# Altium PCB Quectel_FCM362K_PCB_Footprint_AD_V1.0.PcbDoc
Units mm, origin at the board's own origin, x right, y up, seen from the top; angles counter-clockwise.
Board outline 152.4 x 101.6 mm, 2 copper layers (Top Layer, Bottom Layer); 1 components, 0 nets, 47 pads, 0 vias.
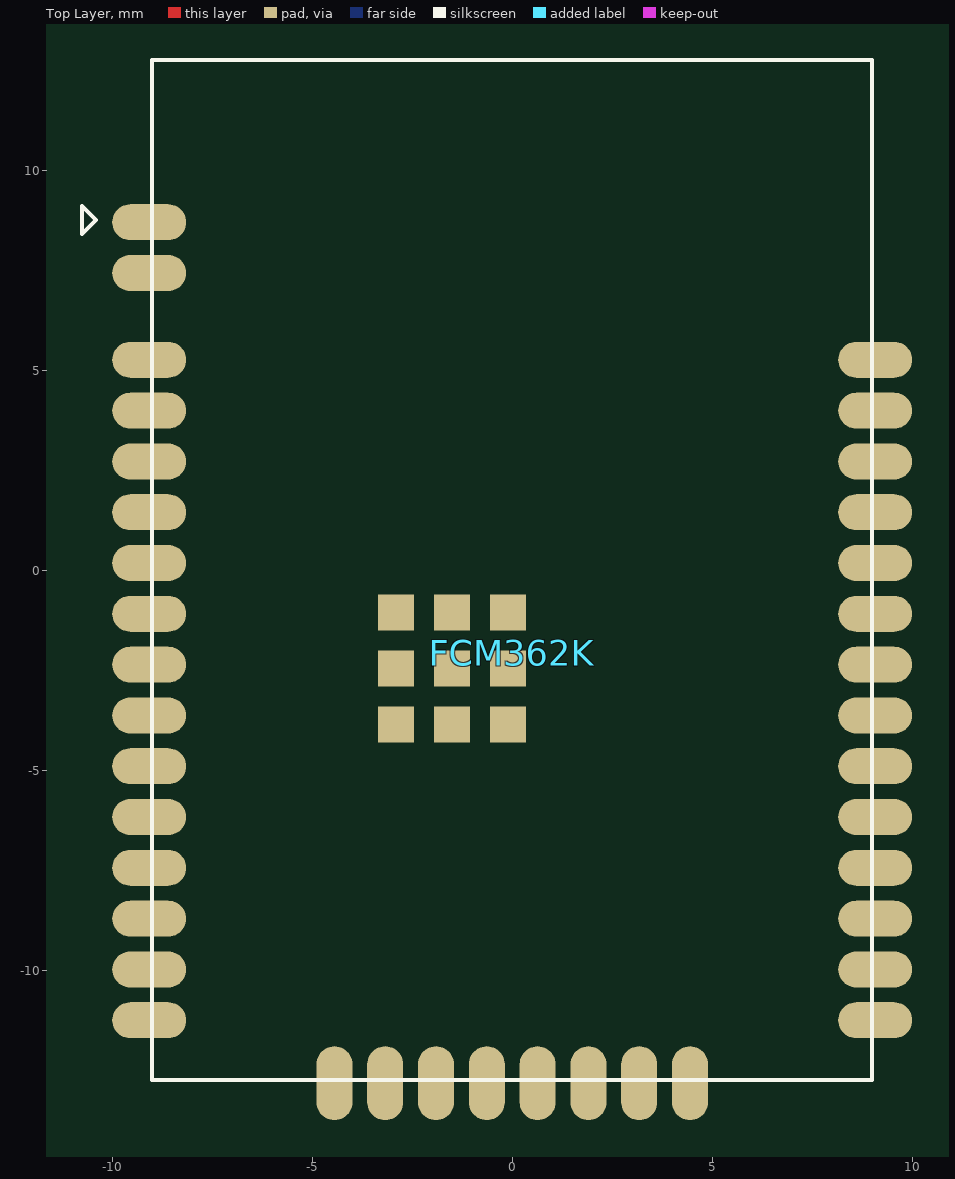
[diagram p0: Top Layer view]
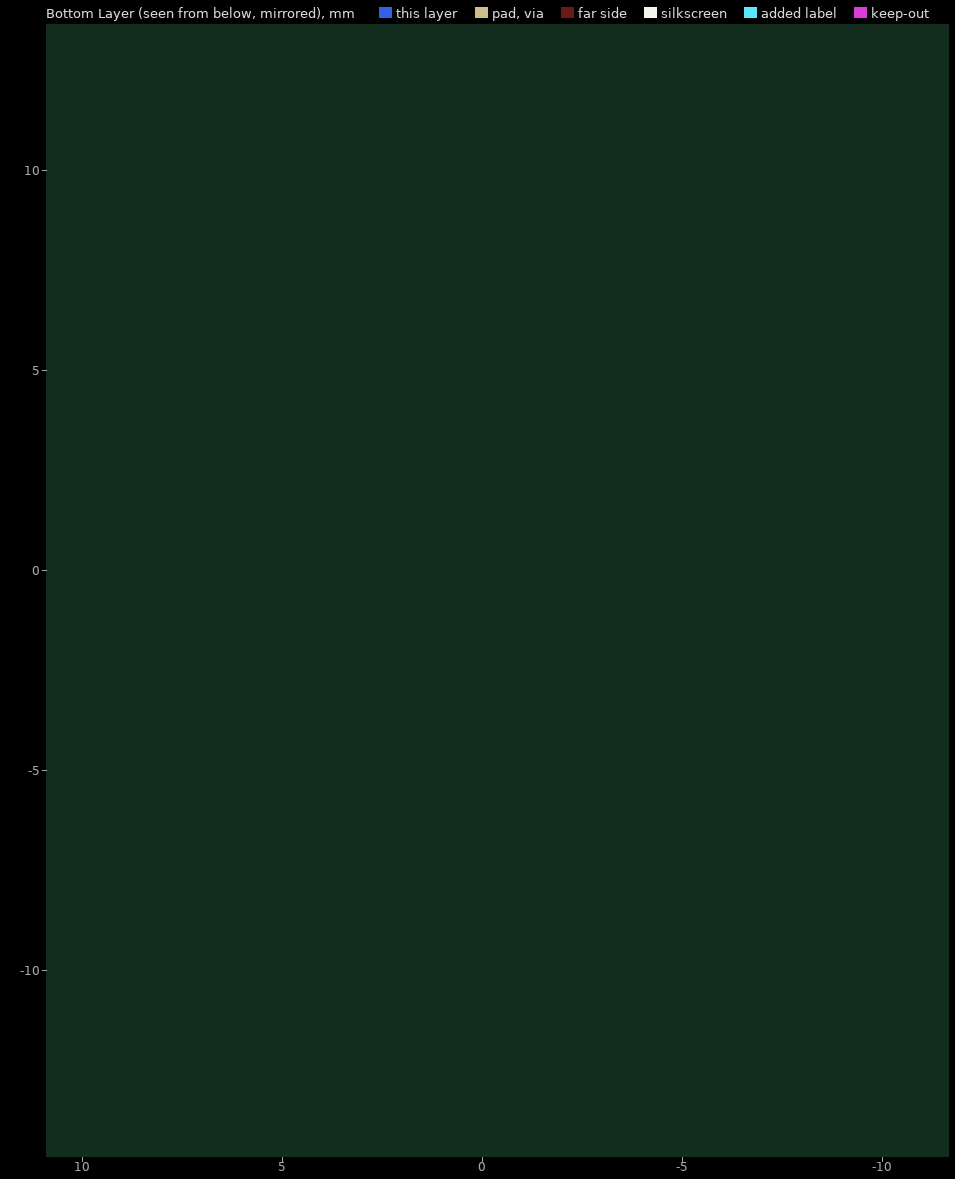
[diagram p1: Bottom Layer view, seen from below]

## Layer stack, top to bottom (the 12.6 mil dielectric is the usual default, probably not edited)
Top Layer: signal copper 0.0356
Dielectric: dielectric 0.32, FR-4, Dk 4.8
Bottom Layer: signal copper 0.0356

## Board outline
-76.708,-55.372 75.692,-55.372 75.692,46.228 -76.708,46.228

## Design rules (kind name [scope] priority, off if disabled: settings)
Clearance [All] p1: gap=0.254
PolygonConnect [All] p1: connectstyle=Relief reliefconductorwidth=0.254 reliefentries=4 polygonreliefangle="90 Angle" airgapwidth=0.254
RoutingVias [All] p1: holewidth=0.711 width=1.27 viastyle="Through Hole" minholewidth=0.711 minwidth=1.27 maxholewidth=0.711 maxwidth=1.27
SolderMaskExpansion [All] p1: expansion=0.102
Width [All] p1: maxlimit=0.254 minlimit=0.254 preferedwidth=0.254
28 further rules are at their usual default settings.

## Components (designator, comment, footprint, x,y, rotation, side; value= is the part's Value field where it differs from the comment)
FCM362K "Comment" FCM362K 0,0 r0 top

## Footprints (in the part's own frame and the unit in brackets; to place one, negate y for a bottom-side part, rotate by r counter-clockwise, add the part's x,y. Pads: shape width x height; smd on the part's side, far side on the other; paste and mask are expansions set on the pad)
FCM362K [mm] "FCM362K Module 47PIN 25.5X18mm H3.15mm RO"
  oval 1.85x0.9 smd mask+0.05: 1(-9.075,8.7) 2(-9.075,7.43) 3(-9.075,5.26) 4(-9.075,3.99) 5(-9.075,2.72) 6(-9.075,1.45) 7(-9.075,0.18) 8(-9.075,-1.09) 9(-9.075,-2.36) 10(-9.075,-3.63) 11(-9.075,-4.9) 12(-9.075,-6.17) 13(-9.075,-7.44) 14(-9.075,-8.71) 15(-9.075,-9.98) 16(-9.075,-11.25) 25(9.075,-11.25) 26(9.075,-9.98) 27(9.075,-8.71) 28(9.075,-7.44) 29(9.075,-6.17) 30(9.075,-4.9) 31(9.075,-3.63) 32(9.075,-2.36) 33(9.075,-1.09) 34(9.075,0.18) 35(9.075,1.45) 36(9.075,2.72) 37(9.075,3.99) 38(9.075,5.26)
  oval 0.9x1.85 smd mask+0.05: 17(-4.445,-12.825) 18(-3.175,-12.825) 19(-1.905,-12.825) 20(-0.635,-12.825) 21(0.635,-12.825) 22(1.905,-12.825) 23(3.175,-12.825) 24(4.445,-12.825)
  rect 0.9x0.9 smd mask+0.05: 39(-2.9,-1.06) 40(-2.9,-2.46) 41(-2.9,-3.86) 42(-1.5,-1.06) 43(-1.5,-2.46) 44(-1.5,-3.86) 45(-0.1,-1.06) 46(-0.1,-2.46) 47(-0.1,-3.86)
  silkscreen extent -10.75,-12.75 9,12.75

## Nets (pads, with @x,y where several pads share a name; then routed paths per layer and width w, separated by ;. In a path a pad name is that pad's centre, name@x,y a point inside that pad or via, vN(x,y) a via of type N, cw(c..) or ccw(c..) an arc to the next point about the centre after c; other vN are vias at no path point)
pads on no net: FCM362K.1 FCM362K.2 FCM362K.3 FCM362K.4 FCM362K.5 FCM362K.6 FCM362K.7 FCM362K.8 FCM362K.9 FCM362K.10 FCM362K.11 FCM362K.12 FCM362K.13 FCM362K.14 FCM362K.15 FCM362K.16 FCM362K.17 FCM362K.18 FCM362K.19 FCM362K.20 FCM362K.21 FCM362K.22 FCM362K.23 FCM362K.24 FCM362K.25 FCM362K.26 FCM362K.27 FCM362K.28 FCM362K.29 FCM362K.30 FCM362K.31 FCM362K.32 FCM362K.33 FCM362K.34 FCM362K.35 FCM362K.36 FCM362K.37 FCM362K.38 FCM362K.39 FCM362K.40 FCM362K.41 FCM362K.42 FCM362K.43 FCM362K.44 FCM362K.45 FCM362K.46 FCM362K.47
